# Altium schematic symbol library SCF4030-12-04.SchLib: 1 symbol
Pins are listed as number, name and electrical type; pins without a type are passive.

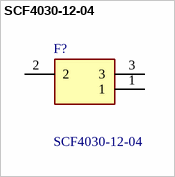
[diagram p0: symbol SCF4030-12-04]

## SCF4030-12-04
designator F?
12A 36 VDC Fuse Board Mount Surface Mount; Manufacturer_Name: Eaton; Geometry.Height: 1mm
footprint SCF40301204
pins: 1, 2, 3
